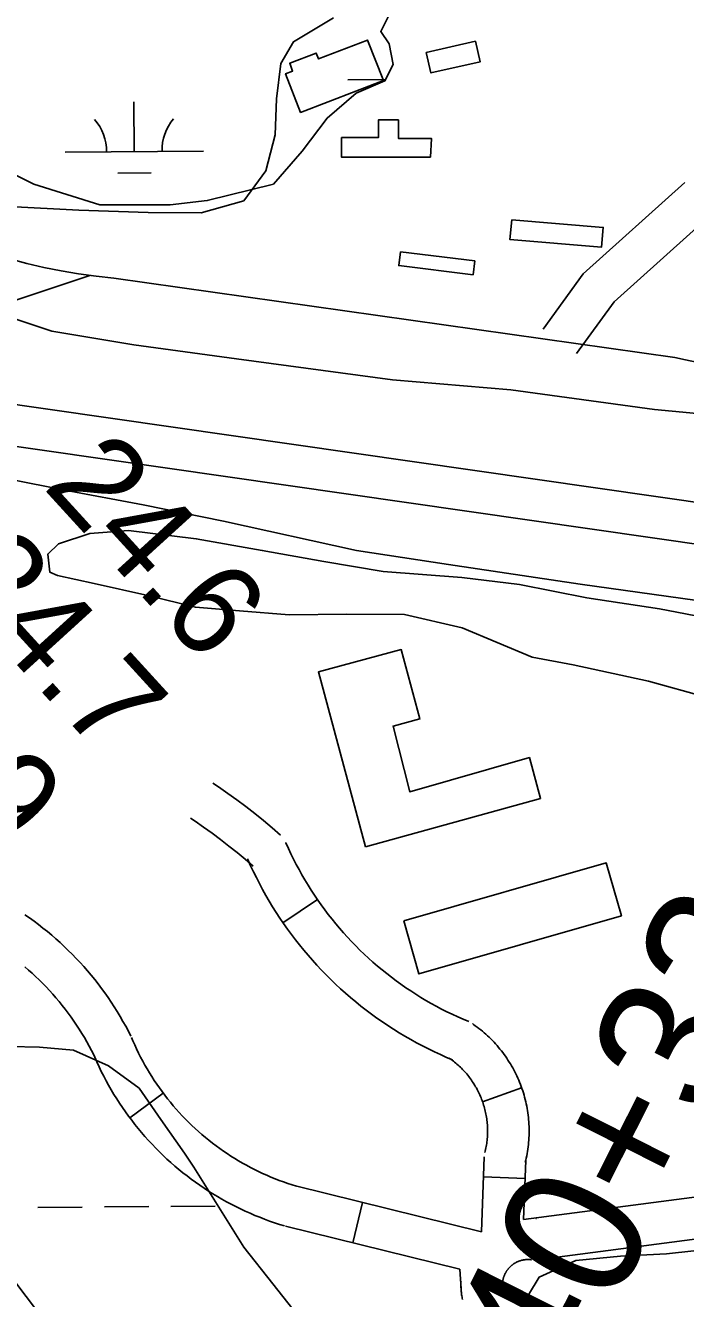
# Model space of a CAD drawing. Extents: x 3540316 to 3578335, y 553172 to 578787.
# Drawn here: x 3551653 to 3552129, y 565162 to 566083 of the extents above; entities that cross this region are included whole.
import ezdxf

# ---------------------------------------------------------------- set-up
doc = ezdxf.new("R2010")
doc.units = 0
for name, color, linetype in [('V-BLDG-OTLN', 7, 'Continuous'), ('V-LEVE-TOET', 7, 'Continuous'), ('V-RIVR-RANG', 7, 'Continuous'), ('V-ROAD-CNTR', 7, 'Continuous'), ('V-SITE-VEGE', 7, 'Continuous'), ('V-SURV-IDEN', 7, 'Continuous'), ('V-SURV-LINE', 7, 'Continuous'), ('V-TOPO-MINR', 7, 'Continuous'), ('V-WETL-SWMP', 7, 'Continuous')]:
    doc.layers.add(name, color=color, linetype=linetype)

msp = doc.modelspace()

# ---------------------------------------------------------------- linework, layer by layer
at = {"layer": 'V-BLDG-OTLN'}
for points in [[(3551911.03, 566043.08), (3551851.2, 566019.93), (3551840.41, 566047.92), (3551845.48, 566049.88), (3551843.34, 566055.44), (3551862.45, 566062.8), (3551864.08, 566058.56), (3551899.46, 566072.24)], [(3551941.86, 566063.29), (3551977.48, 566071.38), (3551980.86, 566056.5), (3551945.37, 566048.44)], [(3551945.13, 565987.65), (3551880.83, 565987.59), (3551880.83, 566001.75), (3551907.38, 566001.76), (3551907.36, 566014.47), (3551921.82, 566014.47), (3551921.84, 566001.12), (3551945.83, 566001.07)], [(3552003.87, 565942.18), (3552069.77, 565936.76), (3552068.6, 565922.56), (3552002.41, 565928.01)], [(3551923.26, 565919.27), (3551977.02, 565912.59), (3551975.77, 565902.56), (3551922.06, 565909.24)], [(3551897.97, 565488.98), (3551864.08, 565615.56), (3551923.96, 565631.59), (3551937.38, 565581.46), (3551918.01, 565576.27), (3551930.13, 565528.77), (3552016.5, 565553.54), (3552024.56, 565523.85)], [(3551925.8, 565435.57), (3552071.94, 565477.44), (3552082.92, 565439.16), (3551936.49, 565397.2)]]:
    msp.add_lwpolyline(points, close=True, dxfattribs=at)
at = {"layer": 'V-LEVE-TOET'}
for points in [[(3551590.36, 565883.87), (3551612.69, 565884.02), (3551624.49, 565877.44), (3551671.61, 565861.71), (3551730.84, 565851.93), (3551804.96, 565841.87), (3551917.51, 565826.59), (3552002.96, 565819.35), (3552106.89, 565805.18), (3552180.59, 565798.25), (3552231.59, 565788.42), (3552278.34, 565770.33), (3552336.1, 565746.04), (3552427.65, 565707.89), (3552496.47, 565671.54), (3552608.48, 565620.99), (3552652.88, 565602.5), (3552712.22, 565576.27), (3552763.71, 565552.34), (3552793.21, 565538.83)], [(3551431.74, 565810.36), (3551437.74, 565803.96), (3551458.34, 565798.72), (3551472.54, 565796.37), (3551483.53, 565794.1), (3551520.45, 565781.82), (3551558.91, 565771.51), (3551600.89, 565762.79), (3551680.93, 565746.89), (3551737.42, 565736.31), (3551795.49, 565724.57), (3551891.62, 565703.3), (3551957.91, 565693.18), (3552053.21, 565678.95), (3552137.52, 565667), (3552200.69, 565655.3), (3552255.26, 565638.04), (3552319.71, 565609.89), (3552384.16, 565581.74), (3552449.42, 565549.28), (3552496.24, 565521.4), (3552526.53, 565503.58)]]:
    msp.add_lwpolyline(points, dxfattribs=at)
at = {"layer": 'V-ROAD-CNTR'}
for p, q in [((3551863.38, 565450.97), (3551838.5, 565434.2)), ((3551751.98, 565311.03), (3551727.93, 565293.1)), ((3552010.85, 565314.86), (3551982.6, 565304.77)), ((3551983.36, 565250.36), (3552013.34, 565249.27)), ((3551896.03, 565231.91), (3551888.84, 565202.79))]:
    msp.add_line(p, q, dxfattribs=at)
for points in [[(3552026.3, 565863.34), (3552055.33, 565903.18), (3552128.77, 565969.39)], [(3552050.55, 565845.67), (3552077.74, 565882.99), (3552148.86, 565947.11)], [(3551484.98, 565835.83), (3551574.08, 565860.25), (3551698.95, 565902.13)], [(3551716.36, 565900.2), (3552121.4, 565842.73)], [(3551787.89, 565535.17), (3551792.03, 565532.39), (3551798.67, 565527.7), (3551805.17, 565523), (3551811.69, 565518.11), (3551818.07, 565513.08), (3551824.34, 565508.04), (3551830.57, 565502.84), (3551836.62, 565497.55)], [(3551771.82, 565509.82), (3551775.01, 565507.68), (3551781.22, 565503.29), (3551787.38, 565498.84), (3551793.4, 565494.32), (3551799.39, 565489.61), (3551805.32, 565484.84), (3551811.09, 565480.02), (3551816.88, 565474.96)], [(3551840.5, 565492.25), (3551840.65, 565491.9), (3551842.42, 565487.93), (3551844.27, 565484.04), (3551846.15, 565480.16), (3551848.11, 565476.35), (3551850.14, 565472.52), (3551852.2, 565468.82), (3551854.38, 565465.09), (3551856.62, 565461.36), (3551858.87, 565457.75), (3551861.22, 565454.17), (3551863.66, 565450.55), (3551866.11, 565447.05), (3551868.63, 565443.6), (3551871.23, 565440.18), (3551873.91, 565436.76), (3551876.59, 565433.43), (3551879.35, 565430.17), (3551882.18, 565426.92), (3551885.08, 565423.72), (3551888.01, 565420.57), (3551891, 565417.5), (3551894.06, 565414.44), (3551897.13, 565411.48), (3551900.29, 565408.56), (3551903.5, 565405.68), (3551906.75, 565402.85), (3551910.03, 565400.11), (3551913.38, 565397.4), (3551916.78, 565394.78), (3551920.25, 565392.16), (3551923.7, 565389.65), (3551927.2, 565387.2), (3551930.78, 565384.82), (3551934.4, 565382.47), (3551938.07, 565380.18), (3551941.75, 565377.97), (3551945.43, 565375.85), (3551949.22, 565373.78), (3551953.04, 565371.74), (3551956.83, 565369.81), (3551960.73, 565367.94), (3551964.66, 565366.1), (3551968.54, 565364.37), (3551972.6, 565362.67)], [(3551813, 565480.26), (3551813.2, 565479.81), (3551815.16, 565475.41), (3551817.22, 565471.07), (3551819.31, 565466.76), (3551821.52, 565462.46), (3551823.78, 565458.19), (3551826.14, 565453.96), (3551828.56, 565449.8), (3551831.02, 565445.71), (3551833.6, 565441.57), (3551836.25, 565437.54), (3551838.93, 565433.56), (3551841.71, 565429.59), (3551844.57, 565425.68), (3551847.47, 565421.86), (3551850.42, 565418.1), (3551853.46, 565414.32), (3551856.6, 565410.62), (3551859.75, 565407), (3551862.99, 565403.43), (3551866.29, 565399.88), (3551869.65, 565396.42), (3551873.04, 565393.04), (3551876.52, 565389.68), (3551880.08, 565386.39), (3551883.63, 565383.2), (3551887.29, 565380.01), (3551890.99, 565376.93), (3551894.76, 565373.87), (3551898.57, 565370.93), (3551902.39, 565368.05), (3551906.28, 565365.22), (3551910.29, 565362.42), (3551914.29, 565359.75), (3551918.3, 565357.15), (3551922.41, 565354.59), (3551926.53, 565352.12), (3551930.75, 565349.68), (3551934.98, 565347.37), (3551939.18, 565345.13), (3551943.52, 565342.92), (3551947.88, 565340.83), (3551952.2, 565338.81), (3551956.63, 565336.83), (3551961, 565335)], [(3551652.1, 565439.96), (3551655.46, 565437.64), (3551658.76, 565435.23), (3551661.99, 565432.8), (3551665.19, 565430.3), (3551668.37, 565427.75), (3551671.48, 565425.13), (3551674.53, 565422.5), (3551677.56, 565419.78), (3551680.55, 565416.99), (3551683.44, 565414.2), (3551686.34, 565411.33), (3551689.16, 565408.41), (3551691.95, 565405.42), (3551694.66, 565402.41), (3551697.31, 565399.38), (3551699.92, 565396.28), (3551702.53, 565393.08), (3551705.01, 565389.88), (3551707.43, 565386.69), (3551709.84, 565383.39), (3551712.17, 565380.09), (3551714.47, 565376.69), (3551716.68, 565373.27), (3551718.81, 565369.89), (3551720.93, 565366.37), (3551722.96, 565362.84), (3551724.91, 565359.34), (3551726.85, 565355.74), (3551728.65, 565352.19)], [(3551652.01, 565402.31), (3551654.71, 565399.97), (3551657.32, 565397.64), (3551659.9, 565395.22), (3551662.46, 565392.76), (3551664.98, 565390.26), (3551667.42, 565387.73), (3551669.84, 565385.15), (3551672.2, 565382.52), (3551674.56, 565379.82), (3551676.83, 565377.14), (3551679.04, 565374.42), (3551681.21, 565371.62), (3551683.36, 565368.78), (3551685.46, 565365.91), (3551687.49, 565363.02), (3551689.45, 565360.14), (3551691.37, 565357.15), (3551693.28, 565354.13), (3551695.09, 565351.14), (3551696.86, 565348.05), (3551698.6, 565344.93), (3551700.25, 565341.86), (3551701.9, 565338.61)], [(3551975.3, 565361.2), (3551976.03, 565360.69), (3551977.37, 565359.74), (3551978.67, 565358.77), (3551979.97, 565357.78), (3551981.27, 565356.74), (3551982.53, 565355.71), (3551983.77, 565354.65), (3551985.03, 565353.55), (3551986.25, 565352.41), (3551987.41, 565351.32), (3551988.57, 565350.18), (3551989.75, 565348.99), (3551990.9, 565347.78), (3551991.98, 565346.6), (3551993.08, 565345.36), (3551994.17, 565344.07), (3551995.19, 565342.84), (3551996.2, 565341.57), (3551997.23, 565340.24), (3551998.2, 565338.92), (3551999.16, 565337.58), (3552000.08, 565336.24), (3552000.98, 565334.9), (3552001.89, 565333.46), (3552002.74, 565332.08), (3552003.56, 565330.69), (3552004.4, 565329.21), (3552005.17, 565327.79), (3552005.92, 565326.36), (3552006.66, 565324.87), (3552007.37, 565323.39), (3552008.07, 565321.87), (3552008.71, 565320.38), (3552009.33, 565318.9), (3552009.95, 565317.33), (3552010.52, 565315.78), (3552011.06, 565314.27), (3552011.6, 565312.69), (3552012.1, 565311.09), (3552012.56, 565309.54), (3552012.99, 565308), (3552013.41, 565306.38), (3552013.8, 565304.76), (3552014.15, 565303.17), (3552014.48, 565301.56), (3552014.78, 565299.94), (3552015.05, 565298.31), (3552015.29, 565296.72), (3552015.52, 565295.07), (3552015.7, 565293.41), (3552015.86, 565291.82), (3552015.99, 565290.17), (3552016.09, 565288.52), (3552016.17, 565286.86), (3552016.2, 565285.22), (3552016.22, 565283.63), (3552016.21, 565281.98), (3552016.17, 565280.28), (3552016.09, 565278.65), (3552016, 565277.05), (3552015.87, 565275.4), (3552015.72, 565273.77), (3552015.53, 565272.09), (3552015.31, 565270.47), (3552015.08, 565268.89), (3552014.8, 565267.23), (3552014.5, 565265.61), (3552014.19, 565264.05), (3552013.83, 565262.41), (3552013.46, 565260.9)], [(3551729.08, 565351.27), (3551730.1, 565348.88), (3551731.41, 565345.89), (3551732.79, 565342.92), (3551734.21, 565339.96), (3551735.67, 565337.08), (3551737.2, 565334.18), (3551738.78, 565331.31), (3551740.38, 565328.5), (3551742.08, 565325.69), (3551743.79, 565322.9), (3551745.57, 565320.17), (3551747.39, 565317.42), (3551749.22, 565314.8), (3551751.16, 565312.13), (3551753.13, 565309.48), (3551755.1, 565306.93), (3551757.15, 565304.41), (3551759.28, 565301.85), (3551761.39, 565299.39), (3551763.55, 565296.98), (3551765.78, 565294.59), (3551768.07, 565292.19), (3551770.34, 565289.89), (3551772.67, 565287.64), (3551775.06, 565285.39), (3551777.5, 565283.19), (3551779.95, 565281.04), (3551782.44, 565278.95), (3551784.99, 565276.86), (3551787.53, 565274.86), (3551790.13, 565272.89), (3551792.79, 565270.95), (3551795.45, 565269.06), (3551798.14, 565267.25), (3551800.87, 565265.45), (3551803.64, 565263.72), (3551806.47, 565262.01), (3551809.27, 565260.37), (3551812.09, 565258.79), (3551814.98, 565257.26), (3551817.9, 565255.75), (3551820.85, 565254.3), (3551823.8, 565252.91), (3551826.73, 565251.59), (3551829.75, 565250.31), (3551832.8, 565249.06), (3551835.81, 565247.89), (3551838.89, 565246.77), (3551842.01, 565245.68), (3551845.07, 565244.66), (3551848.29, 565243.68)], [(3551701.47, 565339.53), (3551702.55, 565336.99), (3551704.08, 565333.51), (3551705.67, 565330.1), (3551707.29, 565326.71), (3551709.04, 565323.27), (3551710.79, 565319.95), (3551712.6, 565316.66), (3551714.51, 565313.31), (3551716.45, 565310.09), (3551718.42, 565306.88), (3551720.49, 565303.7), (3551722.59, 565300.54), (3551724.78, 565297.41), (3551726.99, 565294.35), (3551729.23, 565291.35), (3551731.57, 565288.31), (3551733.97, 565285.36), (3551736.37, 565282.48), (3551738.85, 565279.58), (3551741.4, 565276.74), (3551743.97, 565273.99), (3551746.56, 565271.29), (3551749.24, 565268.57), (3551751.98, 565265.92), (3551754.73, 565263.33), (3551757.54, 565260.8), (3551760.4, 565258.28), (3551763.3, 565255.85), (3551766.21, 565253.47), (3551769.2, 565251.11), (3551772.24, 565248.81), (3551775.26, 565246.6), (3551778.37, 565244.4), (3551781.51, 565242.28), (3551784.7, 565240.18), (3551787.9, 565238.18), (3551791.11, 565236.23), (3551794.38, 565234.32), (3551797.74, 565232.45), (3551801.07, 565230.67), (3551804.4, 565228.96), (3551807.82, 565227.28), (3551811.23, 565225.67), (3551814.72, 565224.09), (3551818.22, 565222.62), (3551821.67, 565221.2), (3551825.24, 565219.81), (3551828.81, 565218.51), (3551832.34, 565217.28), (3551835.96, 565216.08), (3551839.51, 565214.99)], [(3551958.31, 565336.47), (3551958.82, 565336.12), (3551959.72, 565335.48), (3551960.64, 565334.79), (3551961.53, 565334.12), (3551962.4, 565333.42), (3551963.27, 565332.7), (3551964.13, 565331.97), (3551964.96, 565331.25), (3551965.76, 565330.51), (3551966.61, 565329.7), (3551967.41, 565328.91), (3551968.18, 565328.14), (3551968.93, 565327.34), (3551969.73, 565326.47), (3551970.46, 565325.65), (3551971.16, 565324.83), (3551971.9, 565323.93), (3551972.61, 565323.04), (3551973.26, 565322.2), (3551973.94, 565321.28), (3551974.59, 565320.37), (3551975.23, 565319.43), (3551975.86, 565318.49), (3551976.44, 565317.58), (3551977.03, 565316.61), (3551977.61, 565315.63), (3551978.15, 565314.69), (3551978.68, 565313.69), (3551979.21, 565312.69), (3551979.71, 565311.69), (3551980.2, 565310.67), (3551980.64, 565309.69), (3551981.1, 565308.64), (3551981.55, 565307.57), (3551981.94, 565306.57), (3551982.33, 565305.53), (3551982.72, 565304.43), (3551983.07, 565303.4), (3551983.4, 565302.35), (3551983.72, 565301.27), (3551984.03, 565300.14), (3551984.31, 565299.09), (3551984.56, 565298.02), (3551984.81, 565296.92), (3551985.03, 565295.81), (3551985.24, 565294.71), (3551985.42, 565293.62), (3551985.59, 565292.48), (3551985.74, 565291.4), (3551985.86, 565290.3), (3551985.97, 565289.15), (3551986.07, 565288.04), (3551986.13, 565286.94), (3551986.18, 565285.82), (3551986.21, 565284.71), (3551986.22, 565283.54), (3551986.22, 565282.43), (3551986.19, 565281.36), (3551986.14, 565280.24), (3551986.07, 565279.09), (3551985.98, 565277.96), (3551985.88, 565276.85), (3551985.76, 565275.78), (3551985.6, 565274.66), (3551985.44, 565273.51), (3551985.26, 565272.45), (3551985.05, 565271.34), (3551984.82, 565270.2), (3551984.59, 565269.14), (3551984.31, 565267.96)], [(3551981.92, 565210.7), (3551983.89, 565264.98)], [(3552012.26, 565219.54), (3552013.82, 565262.37)], [(3551847.49, 565243.9), (3551981.92, 565210.7)], [(3552222.06, 565247.02), (3552012.26, 565219.54)], [(3551840.3, 565214.77), (3551966.33, 565183.65)], [(3552021.67, 565220.28), (3552021.1, 565220.35)], [(3552225.95, 565217.28), (3552021.74, 565190.53)], [(3552017.92, 565190.52), (3552017.5, 565190.57), (3552017.22, 565190.6), (3552016.85, 565190.63), (3552016.52, 565190.66), (3552016.26, 565190.67), (3552015.88, 565190.68), (3552015.56, 565190.69), (3552015.28, 565190.69), (3552014.95, 565190.68), (3552014.63, 565190.67), (3552014.29, 565190.65), (3552013.96, 565190.63), (3552013.67, 565190.61), (3552013.37, 565190.57), (3552013.01, 565190.53), (3552012.68, 565190.49), (3552012.39, 565190.44), (3552012.07, 565190.38), (3552011.76, 565190.32), (3552011.42, 565190.25), (3552011.12, 565190.18), (3552010.83, 565190.11), (3552010.5, 565190.02), (3552010.21, 565189.94), (3552009.9, 565189.84), (3552009.58, 565189.74), (3552009.26, 565189.63), (3552008.98, 565189.53), (3552008.71, 565189.43), (3552008.36, 565189.28), (3552008.05, 565189.16), (3552007.79, 565189.04), (3552007.52, 565188.91), (3552007.19, 565188.75), (3552006.91, 565188.61), (3552006.67, 565188.48), (3552006.35, 565188.3), (3552006.06, 565188.14), (3552005.82, 565188), (3552005.53, 565187.81), (3552005.27, 565187.65), (3552005, 565187.46), (3552004.71, 565187.26), (3552004.49, 565187.1), (3552004.22, 565186.89), (3552003.95, 565186.69), (3552003.73, 565186.51), (3552003.47, 565186.29), (3552003.22, 565186.07), (3552002.98, 565185.86), (3552002.74, 565185.64), (3552002.54, 565185.44), (3552002.29, 565185.19), (3552002.04, 565184.94), (3552001.86, 565184.74), (3552001.65, 565184.51), (3552001.4, 565184.22), (3552001.22, 565184), (3552001.03, 565183.77), (3552000.82, 565183.5), (3552000.61, 565183.22), (3552000.43, 565182.98), (3552000.26, 565182.74), (3552000.07, 565182.46), (3551999.89, 565182.18), (3551999.72, 565181.91), (3551999.56, 565181.65), (3551999.39, 565181.35), (3551999.24, 565181.09), (3551999.1, 565180.81), (3551998.93, 565180.49), (3551998.8, 565180.21), (3551998.67, 565179.94), (3551998.54, 565179.65), (3551998.41, 565179.35), (3551998.28, 565179.01), (3551998.16, 565178.72), (3551998.07, 565178.48), (3551997.97, 565178.17), (3551997.86, 565177.82), (3551997.76, 565177.5), (3551997.67, 565177.19), (3551997.6, 565176.94), (3551997.52, 565176.62), (3551997.44, 565176.25), (3551997.38, 565175.98), (3551997.32, 565175.66), (3551997.25, 565175.3), (3551997.21, 565175.03), (3551997.16, 565174.71), (3551997.12, 565174.38), (3551997.09, 565174.1), (3551997.06, 565173.74), (3551997.04, 565173.41), (3551997.02, 565173.12), (3551997.01, 565172.76), (3551997, 565172.44), (3551997, 565172.15), (3551997.01, 565171.84), (3551997.02, 565171.52)], [(3551966.33, 565183.65), (3551967.09, 565169.4), (3551967.15, 565168.56), (3551967.22, 565167.66), (3551967.31, 565166.82), (3551967.41, 565166.02), (3551967.53, 565165.18), (3551967.66, 565164.34), (3551967.81, 565163.5), (3551967.97, 565162.66), (3551968.14, 565161.87)], [(3551967.08, 565175.04), (3551967.05, 565174.41), (3551967.02, 565173.61), (3551967, 565172.77), (3551967, 565171.89), (3551967.02, 565171.04), (3551967.05, 565170.18)], [(3551997.02, 565171.52), (3551997.04, 565171.15), (3551997.06, 565170.82), (3551997.08, 565170.56), (3551997.12, 565170.24), (3551997.16, 565169.88), (3551997.2, 565169.57), (3551997.26, 565169.25), (3551997.31, 565168.95), (3551997.37, 565168.65), (3551997.44, 565168.3), (3551997.51, 565168), (3551997.58, 565167.71), (3551997.67, 565167.37), (3551997.76, 565167.07), (3551997.85, 565166.78), (3551997.95, 565166.46), (3551998.06, 565166.14), (3551998.16, 565165.86), (3551998.27, 565165.59), (3551998.4, 565165.24), (3551998.53, 565164.94), (3551998.66, 565164.66), (3551998.78, 565164.4), (3551998.94, 565164.07), (3551999.08, 565163.79), (3551999.07, 565163.82)]]:
    msp.add_lwpolyline(points, dxfattribs=at)
for centre, radius, start, end in [((3551752.09, 566303.1), 404.48, 207.79436, 264.93084), ((3551695.25, 563846.95), 2040.77, 70.76663, 77.94693)]:
    msp.add_arc(centre, radius, start, end, dxfattribs=at)
at = {"layer": 'V-SITE-VEGE'}
for points in [[(3551874.99, 566088.38), (3551846.18, 566071.01), (3551836.97, 566055.25), (3551833.71, 566029.73), (3551832.91, 566003.73), (3551826.23, 565977.69), (3551810.19, 565956), (3551779.36, 565947.45), (3551741.1, 565947.67), (3551691.06, 565949.29), (3551640.53, 565951.88), (3551602.68, 565965.35), (3551574.09, 565985.26), (3551546.46, 566009.59), (3551521.77, 566034.92), (3551491.68, 566058.74), (3551466, 566084.55)], [(3552144.12, 565597.2), (3552102.4, 565608.67), (3552047.94, 565620.54), (3552018.5, 565626.21), (3551967.9, 565647.42), (3551926.19, 565656.93), (3551884.54, 565657.13), (3551842.9, 565656.84), (3551807.12, 565659.53), (3551775.25, 565662.25), (3551740.9, 565670.83), (3551702.14, 565679.38), (3551675.64, 565685.08), (3551670.24, 565687.48), (3551668.67, 565700.7), (3551676.46, 565708.11), (3551698.95, 565715.61), (3551726.85, 565717.77), (3551775.89, 565711.74), (3551823.47, 565703.25), (3551868.11, 565695.23), (3551910.78, 565688.18), (3551967.64, 565683.67), (3552009.32, 565678.58), (3552057.89, 565669.11), (3552110.37, 565661.15), (3552149.12, 565653.58)], [(3552115.56, 565194.78), (3552135.15, 565196.88)], [(3552024.88, 565131.44), (3552015.83, 565165.19), (3552023.58, 565177.98), (3552049.95, 565189.92), (3552082.26, 565193.08), (3552115.56, 565194.78)]]:
    msp.add_lwpolyline(points, dxfattribs=at)
at = {"layer": 'V-SURV-LINE'}
for points in [[(3551494.22, 565830.49), (3552196.61, 565729.59)], [(3552192.37, 565699.89), (3551489.97, 565800.79)]]:
    msp.add_lwpolyline(points, dxfattribs=at)
at = {"layer": 'V-TOPO-MINR'}
msp.add_lwpolyline([(3552450.71, 564051.01), (3552413.55, 564114.44), (3552376.08, 564177.7), (3552333.35, 564249.23), (3552316.58, 564276.29), (3552299.25, 564302.98), (3552281.08, 564329.1), (3552262.33, 564354.83), (3551604.23, 565228.5), (3551581.49, 565257.87), (3551558.25, 565286.81), (3551534.25, 565315.13), (3551509.74, 565343.04), (3551484.58, 565370.36), (3551459.05, 565397.33), (3551432.97, 565423.77), (3551406.52, 565449.85), (3550894.86, 565944.27)], dxfattribs=at)
at = {"layer": 'V-WETL-SWMP'}
for p, q in [((3551885.34, 566043.55), (3551912.65, 566043.76)), ((3551731.14, 565991.62), (3551730.86, 566027.62)), ((3551681.14, 565991.23), (3551781.14, 565992)), ((3551719.26, 565976.09), (3551743.26, 565976.28)), ((3551641.33, 565344.64), (3551662.57, 565344.25)), ((3551662.57, 565344.25), (3551687.2, 565342.01)), ((3551687.2, 565342.01), (3551712.38, 565330.64)), ((3551712.38, 565330.64), (3551734.68, 565314.46)), ((3551734.68, 565314.46), (3551750.28, 565291.96)), ((3551750.28, 565291.96), (3551767.34, 565267.54)), ((3551767.34, 565267.54), (3551774.16, 565257.46)), ((3551774.16, 565257.46), (3551810.27, 565199.53)), ((3551661.58, 565228.39), (3551693.58, 565228.64)), ((3551709.58, 565228.76), (3551741.58, 565229.01)), ((3551757.58, 565229.13), (3551789.58, 565229.38)), ((3551810.27, 565199.53), (3551831.19, 565173.22)), ((3551831.19, 565173.22), (3551849.21, 565150.26))]:
    msp.add_line(p, q, dxfattribs=at)
msp.add_lwpolyline([(3551915.1, 566090.44), (3551909.13, 566078.5), (3551915.1, 566069.55), (3551918.08, 566054.64), (3551912.12, 566042.7), (3551891.23, 566033.75), (3551870.35, 566015.85), (3551852.45, 565991.98), (3551831.56, 565968.11), (3551783.82, 565956.18), (3551756.97, 565953.19), (3551706.25, 565953.19), (3551658.51, 565968.11), (3551616.74, 565989), (3551589.89, 566009.88), (3551554.08, 566054.64), (3551527.23, 566096.41)], dxfattribs=at)
for centre, start, end in [((3551786.38, 565992.52), 139.66985, 181.21351), ((3551675.9, 565991.67), 359.66986, 41.21351)]:
    msp.add_arc(centre, 35.25, start, end, dxfattribs=at)

# ---------------------------------------------------------------- texts
at = {"layer": 'V-RIVR-RANG'}
for s, p in [('24.6', (3551664.36, 565749.14)), ('24.7', (3551591.88, 565680.21)), ('23.9', (3551517.98, 565612.85))]:
    msp.add_text(s, height=67, rotation=312.35833, dxfattribs=at).set_placement(p)
at = {"layer": 'V-SURV-IDEN'}
for s, rotation, p in [('4932+83.4', 66.27903, (3551595.74, 566009.52)), ('4940+33.1', 63.19087, (3551975.53, 564955.23))]:
    msp.add_text(s, height=100, rotation=rotation, dxfattribs=at).set_placement(p)

doc.saveas('drawing.dxf')
